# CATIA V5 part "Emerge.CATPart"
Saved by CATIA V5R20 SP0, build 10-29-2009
Part number: Emerge.SLDASM
Bounding box of the stored display mesh (mm): x -969.019 to 969.019, y -29.495 to 1205.382, z -4464 to 50.323
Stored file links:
  C:\Users\Venkat\Desktop\Emerg-E\Emerge.CATPart
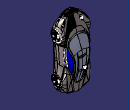
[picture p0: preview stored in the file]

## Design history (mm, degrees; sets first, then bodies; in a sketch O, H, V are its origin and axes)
Set1
  DatumCurve1 to DatumCurve27
  DatumSurface1 to DatumSurface785
  DatumCurve28 to DatumCurve30
  Circle1: stored without definition
  DatumCurve31 to DatumCurve43
  Circle2: stored without definition
  DatumCurve44 to DatumCurve51
  Circle3: stored without definition
  DatumCurve52 to DatumCurve66
  Circle4: stored without definition
  DatumCurve67 to DatumCurve72
  DatumSurface786 to DatumSurface1741
  DatumCurve73 to DatumCurve75
  Circle5: stored without definition
  DatumCurve76 to DatumCurve88
  Circle6: stored without definition
  DatumCurve89 to DatumCurve96
  Circle7: stored without definition
  DatumCurve97 to DatumCurve111
  Circle8: stored without definition
  DatumCurve112 to DatumCurve117
  DatumSurface1742 to DatumSurface2697
  DatumCurve118 to DatumCurve120
  Circle9: stored without definition
  DatumCurve121 to DatumCurve133
  Circle10: stored without definition
  DatumCurve134 to DatumCurve141
  Circle11: stored without definition
  DatumCurve142 to DatumCurve156
  Circle12: stored without definition
  DatumCurve157 to DatumCurve162
  DatumSurface2698 to DatumSurface3652
  DatumCurve163 to DatumCurve165
  Circle13: stored without definition
  DatumCurve166 to DatumCurve178
  Circle14: stored without definition
  DatumCurve179 to DatumCurve186
  Circle15: stored without definition
  DatumCurve187 to DatumCurve201
  Circle16: stored without definition
  DatumCurve202 to DatumCurve207
  DatumSurface3653 to DatumSurface11905
  DatumCurve208 to DatumCurve234
  DatumSurface11906 to DatumSurface12089
Set2 "Geometry Failure"
  Set3 "FaceKO##17267"
    DatumSurface12090 "Sur17267_1"
    DatumSurface12091 "Sur17267_2"
    DatumSurface12092 "Sur17267_3"
    DatumCurve235 "Crv17267_1"
    DatumCurve236 "Crv17267_2"
    DatumCurve237 "Crv17267_3"
    DatumCurve238 "Crv17267_4"
    DatumCurve239 "Crv17267_5"
    DatumCurve240 "Crv17267_6"
    DatumCurve241 "Crv17267_7"
    DatumCurve242 "Crv17267_8"
    DatumCurve243 "Crv17267_9"
    DatumCurve244 "Crv17267_10"
    DatumCurve245 "Crv17267_11"
    DatumCurve246 "Crv17267_12"
    DatumCurve247 "Crv17267_13"
    DatumCurve248 "Crv17267_14"
    DatumCurve249 "Crv17267_15"
    DatumCurve250 "Crv17267_16"
    DatumCurve251 "Crv17267_17"
    DatumCurve252 "Crv17267_18"
    DatumCurve253 "Crv17267_19"
    DatumCurve254 "Crv17267_20"
    DatumCurve255 "Crv17267_21"
    DatumCurve256 "Crv17267_22"
    DatumCurve257 "Crv17267_23"
    DatumCurve258 "Crv17267_24"
    DatumCurve259 "Crv17267_25"
    DatumCurve260 "Crv17267_26"
    DatumCurve261 "Crv17267_27"
    DatumCurve262 "Crv17267_28"
    DatumCurve263 "Crv17267_29"
    DatumCurve264 "Crv17267_30"
    DatumCurve265 "Crv17267_31"
    DatumCurve266 "Crv17267_32"
    DatumCurve267 "PCrv17267_1"
    DatumCurve268 "PCrv17267_2"
    DatumCurve269 "PCrv17267_3"
    DatumCurve270 "PCrv17267_4"
    DatumCurve271 "PCrv17267_5"
    DatumCurve272 "PCrv17267_6"
    DatumCurve273 "PCrv17267_7"
    DatumCurve274 "PCrv17267_8"
    DatumCurve275 "PCrv17267_9"
    DatumCurve276 "PCrv17267_10"
    DatumCurve277 "PCrv17267_11"
    DatumCurve278 "PCrv17267_12"
    DatumCurve279 "PCrv17267_13"
    DatumCurve280 "PCrv17267_14"
    DatumCurve281 "PCrv17267_15"
    DatumCurve282 "PCrv17267_16"
    DatumCurve283 "PCrv17267_17"
    DatumCurve284 "PCrv17267_18"
    DatumCurve285 "PCrv17267_19"
    DatumCurve286 "PCrv17267_20"
    DatumCurve287 "PCrv17267_21"
    DatumCurve288 "PCrv17267_22"
    DatumCurve289 "PCrv17267_23"
    DatumCurve290 "PCrv17267_24"
    DatumCurve291 "PCrv17267_25"
    DatumCurve292 "PCrv17267_26"
    DatumCurve293 "PCrv17267_27"
    DatumCurve294 "PCrv17267_28"
    DatumCurve295 "PCrv17267_29"
    DatumCurve296 "PCrv17267_30"
    DatumCurve297 "PCrv17267_31"
    DatumCurve298 "PCrv17267_32"
    DatumCurve299 "PCrv17267_33"
    DatumCurve300 "PCrv17267_34"
Body1 (main body)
